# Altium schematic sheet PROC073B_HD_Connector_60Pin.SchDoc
size 431 x 279 mm; Date: Not shown in title block; ApprovedBy: Not shown in title block; CheckedBy: Not shown in title block; Author: Not shown in title block; CompanyName: Not shown in title block; Engineer: Not shown in title block; Organization: Not shown in title block; Address1: Not shown in title block; Address2: Not shown in title block; Address3: Not shown in title block; Address4: Not shown in title block; DocumentNumber: 1; Revision: Use project parameter SCH_Rev; SheetNumber: 7; SheetTotal: 9; PageSetup: Record=PageOptions¦CenterHorizontal=True¦CenterVertical=True¦PrintScale=1.00¦XCorrection=1.00¦YCorrection=1.00¦PrintKind=0¦BorderSize=5000000¦LeftOffset=0¦BottomOffset=0¦Orientation=2¦PaperLength=1000¦PaperWidth=1000¦Scale=100¦PaperSource=15¦PrintQuality=600¦MediaType=1¦DitherType=10¦PaperKind=Letter¦PrintScaleMode=1
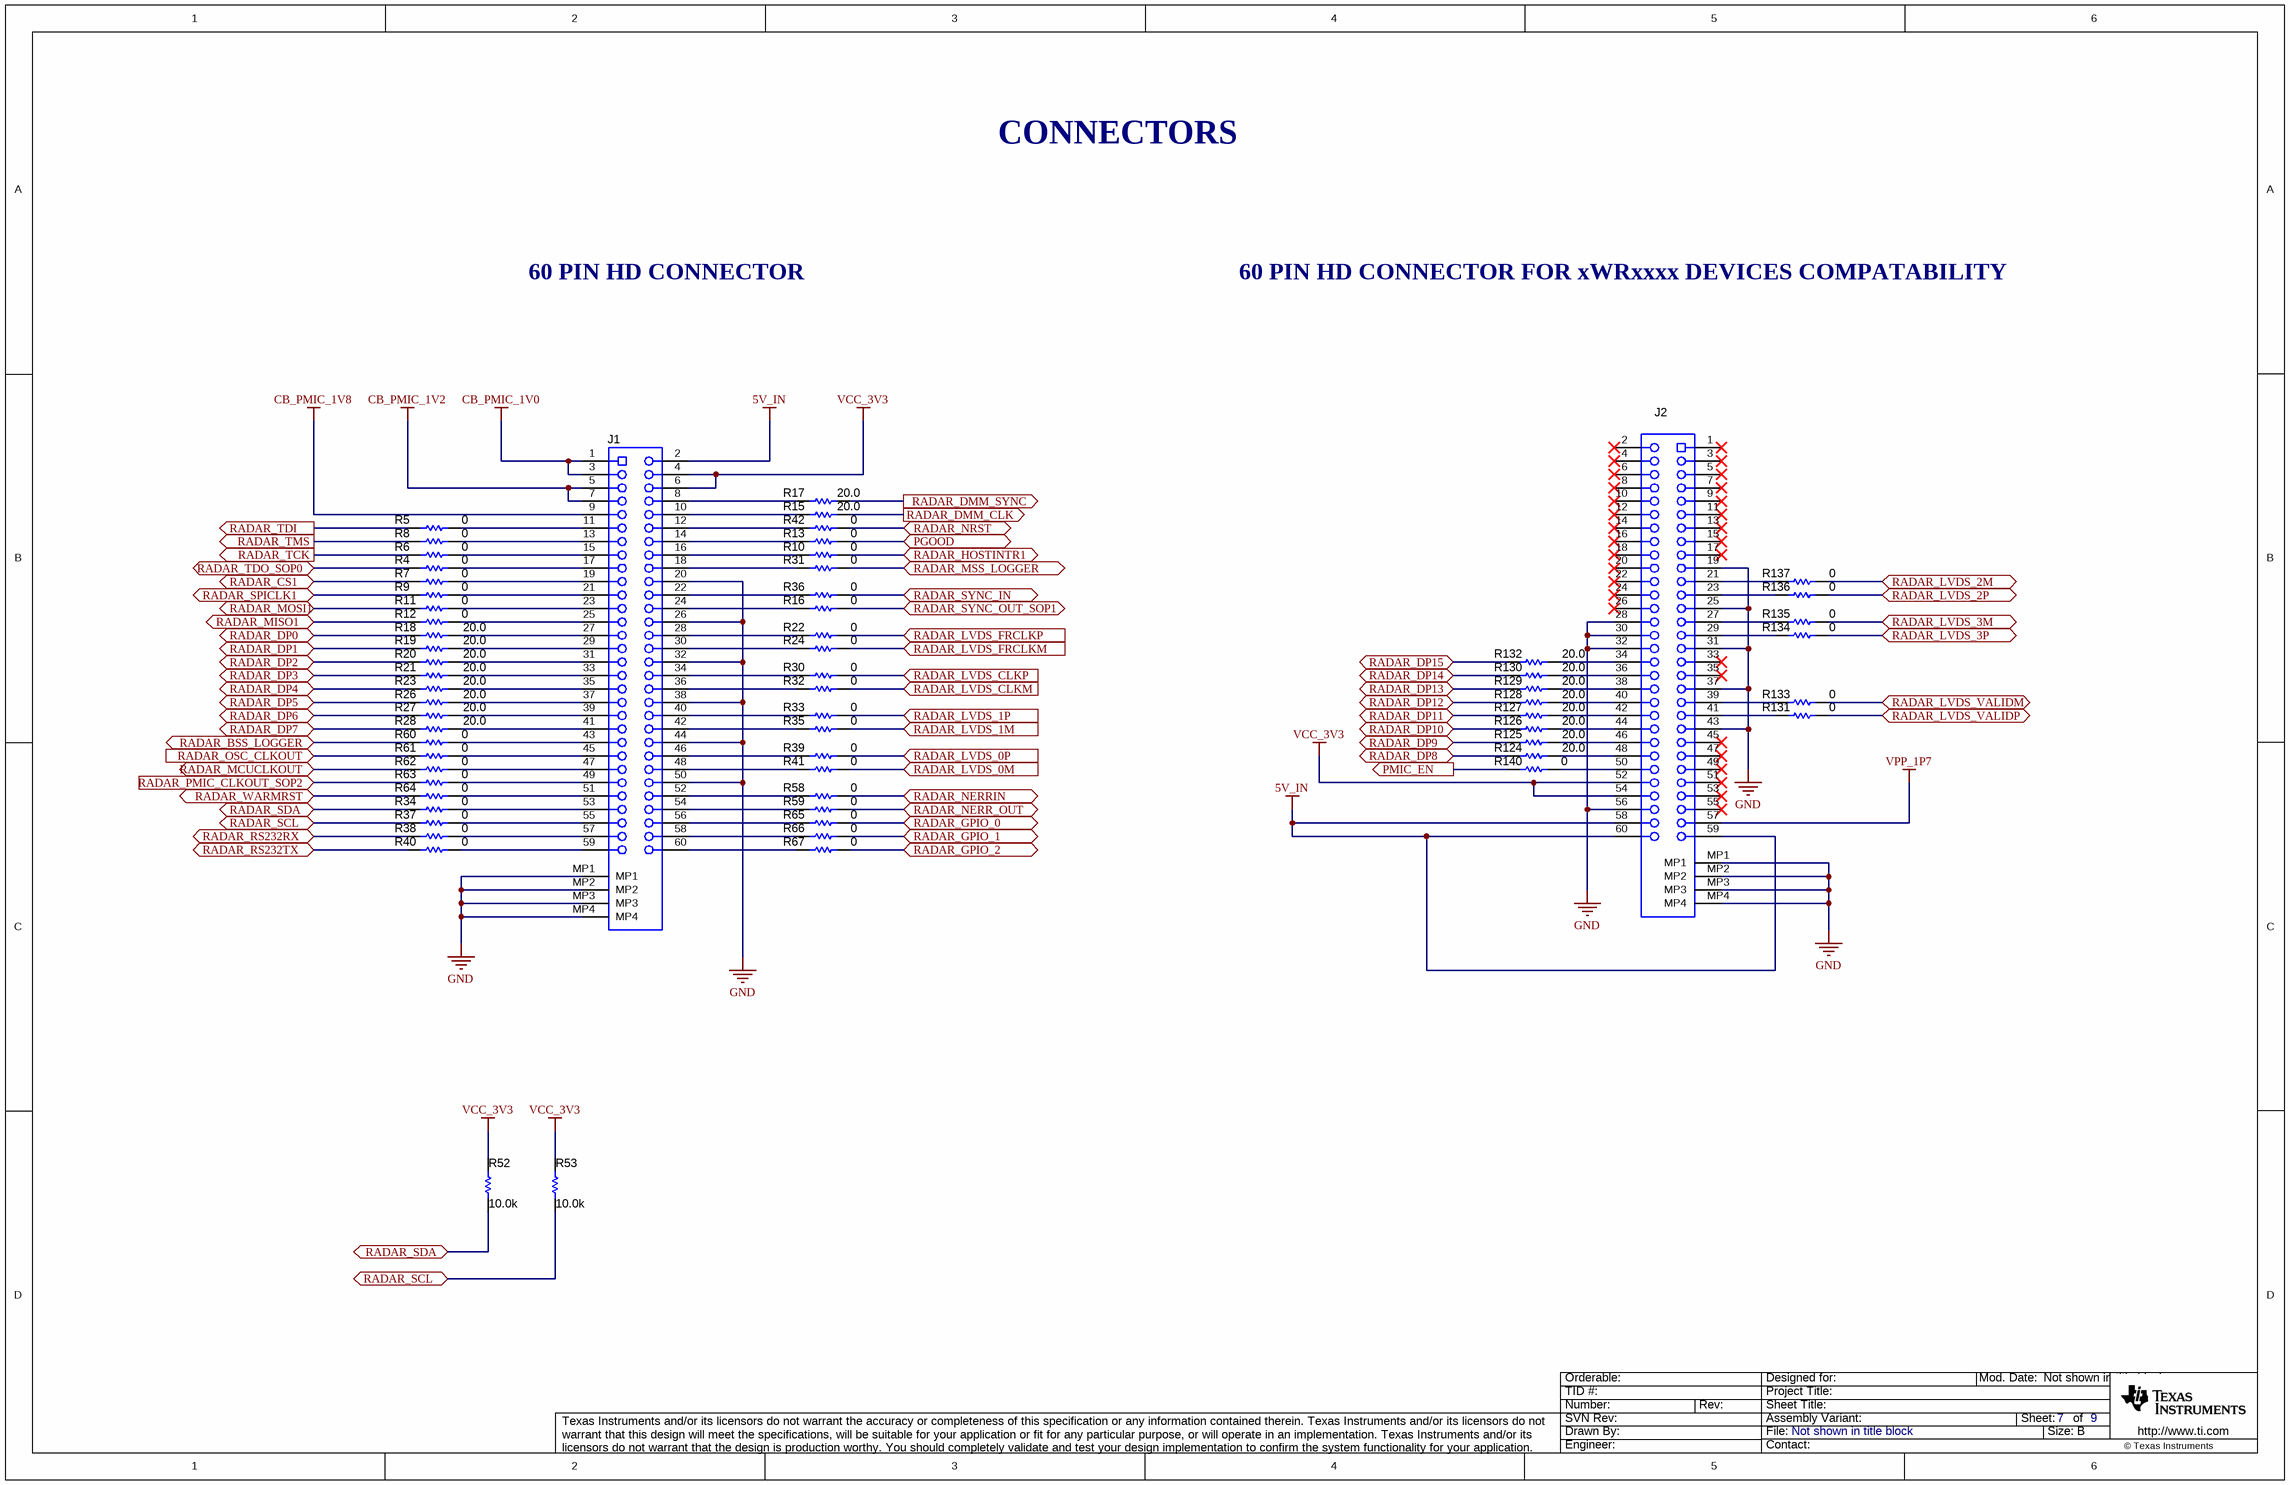
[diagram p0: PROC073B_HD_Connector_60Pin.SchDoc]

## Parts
J1  QSH-030-01-L-D-A  [Samtec_QSH-030-01-X-D-A]  (value not drawn)
J2  QSH-030-01-L-D-A  [Samtec_QSH-030-01-X-D-A]  (value not drawn)
R4  ValueDisplayed: 0  [0201_Silk]  (hidden comment: CRCW02010000Z0ED)
R5  ValueDisplayed: 0  [0201_Silk]  (hidden comment: CRCW02010000Z0ED)
R6  ValueDisplayed: 0  [0201_Silk]  (hidden comment: CRCW02010000Z0ED)
R7  ValueDisplayed: 0  [0201_Silk]  (hidden comment: CRCW02010000Z0ED)
R8  ValueDisplayed: 0  [0201_Silk]  (hidden comment: CRCW02010000Z0ED)
R9  ValueDisplayed: 0  [0201_Silk]  (hidden comment: CRCW02010000Z0ED)
R10  ValueDisplayed: 0  [0201_Silk]  (hidden comment: CRCW02010000Z0ED)
R11  ValueDisplayed: 0  [0201_Silk]  (hidden comment: CRCW02010000Z0ED)
R12  ValueDisplayed: 0  [0201_Silk]  (hidden comment: CRCW02010000Z0ED)
R13  ValueDisplayed: 0  [0201_Silk]  (hidden comment: CRCW02010000Z0ED)
R15  ValueDisplayed: 20.0  [0201_033]  (hidden comment: CRCW020120R0FNED)
R16  ValueDisplayed: 0  [0201_Silk]  (hidden comment: CRCW02010000Z0ED)
R17  ValueDisplayed: 20.0  [0201_033]  (hidden comment: CRCW020120R0FNED)
R18  ValueDisplayed: 20.0  [0201_033]  (hidden comment: CRCW020120R0FNED)
R19  ValueDisplayed: 20.0  [0201_033]  (hidden comment: CRCW020120R0FNED)
R20  ValueDisplayed: 20.0  [0201_033]  (hidden comment: CRCW020120R0FNED)
R21  ValueDisplayed: 20.0  [0201_033]  (hidden comment: CRCW020120R0FNED)
R22  ValueDisplayed: 0  [0201_Silk]  (hidden comment: CRCW02010000Z0ED)
R23  ValueDisplayed: 20.0  [0201_033]  (hidden comment: CRCW020120R0FNED)
R24  ValueDisplayed: 0  [0201_Silk]  (hidden comment: CRCW02010000Z0ED)
R26  ValueDisplayed: 20.0  [0201_033]  (hidden comment: CRCW020120R0FNED)
R27  ValueDisplayed: 20.0  [0201_033]  (hidden comment: CRCW020120R0FNED)
R28  ValueDisplayed: 20.0  [0201_033]  (hidden comment: CRCW020120R0FNED)
R30  ValueDisplayed: 0  [0201_Silk]  (hidden comment: CRCW02010000Z0ED)
R31  ValueDisplayed: 0  [0201_Silk]  (hidden comment: CRCW02010000Z0ED)
R32  ValueDisplayed: 0  [0201_Silk]  (hidden comment: CRCW02010000Z0ED)
R33  ValueDisplayed: 0  [0201_Silk]  (hidden comment: CRCW02010000Z0ED)
R34  ValueDisplayed: 0  [0201_Silk]  (hidden comment: CRCW02010000Z0ED)
R35  ValueDisplayed: 0  [0201_Silk]  (hidden comment: CRCW02010000Z0ED)
R36  ValueDisplayed: 0  [0201_Silk]  (hidden comment: CRCW02010000Z0ED)
R37  ValueDisplayed: 0  [0201_Silk]  (hidden comment: CRCW02010000Z0ED)
R38  ValueDisplayed: 0  [0201_Silk]  (hidden comment: CRCW02010000Z0ED)
R39  ValueDisplayed: 0  [0201_Silk]  (hidden comment: CRCW02010000Z0ED)
R40  ValueDisplayed: 0  [0201_Silk]  (hidden comment: CRCW02010000Z0ED)
R41  ValueDisplayed: 0  [0201_Silk]  (hidden comment: CRCW02010000Z0ED)
R42  ValueDisplayed: 0  [0201_Silk]  (hidden comment: CRCW02010000Z0ED)
R52  ValueDisplayed: 10.0k  [0402L]  (hidden comment: CRCW040210K0FKED)
R53  ValueDisplayed: 10.0k  [0402L]  (hidden comment: CRCW040210K0FKED)
R58  ValueDisplayed: 0  [0201_Silk]  (hidden comment: CRCW02010000Z0ED)
R59  ValueDisplayed: 0  [0201_Silk]  (hidden comment: CRCW02010000Z0ED)
R60  ValueDisplayed: 0  [0201_Silk]  (hidden comment: CRCW02010000Z0ED)
R61  ValueDisplayed: 0  [0201_Silk]  (hidden comment: CRCW02010000Z0ED)
R62  ValueDisplayed: 0  [0201_Silk]  (hidden comment: CRCW02010000Z0ED)
R63  ValueDisplayed: 0  [0201_Silk]  (hidden comment: CRCW02010000Z0ED)
R64  ValueDisplayed: 0  [0201_Silk]  (hidden comment: CRCW02010000Z0ED)
R65  ValueDisplayed: 0  [0201_Silk]  (hidden comment: CRCW02010000Z0ED)
R66  ValueDisplayed: 0  [0201_Silk]  (hidden comment: CRCW02010000Z0ED)
R67  ValueDisplayed: 0  [0201_Silk]  (hidden comment: CRCW02010000Z0ED)
R124  ValueDisplayed: 20.0  [0201_033]  (hidden comment: CRCW020120R0FNED)
R125  ValueDisplayed: 20.0  [0201_033]  (hidden comment: CRCW020120R0FNED)
R126  ValueDisplayed: 20.0  [0201_033]  (hidden comment: CRCW020120R0FNED)
R127  ValueDisplayed: 20.0  [0201_033]  (hidden comment: CRCW020120R0FNED)
R128  ValueDisplayed: 20.0  [0201_033]  (hidden comment: CRCW020120R0FNED)
R129  ValueDisplayed: 20.0  [0201_033]  (hidden comment: CRCW020120R0FNED)
R130  ValueDisplayed: 20.0  [0201_033]  (hidden comment: CRCW020120R0FNED)
R131  ValueDisplayed: 0  [0201_Silk]  (hidden comment: CRCW02010000Z0ED)
R132  ValueDisplayed: 20.0  [0201_033]  (hidden comment: CRCW020120R0FNED)
R133  ValueDisplayed: 0  [0201_Silk]  (hidden comment: CRCW02010000Z0ED)
R134  ValueDisplayed: 0  [0201_Silk]  (hidden comment: CRCW02010000Z0ED)
R135  ValueDisplayed: 0  [0201_Silk]  (hidden comment: CRCW02010000Z0ED)
R136  ValueDisplayed: 0  [0201_Silk]  (hidden comment: CRCW02010000Z0ED)
R137  ValueDisplayed: 0  [0201_Silk]  (hidden comment: CRCW02010000Z0ED)
R140  ValueDisplayed: 0  [0201_Silk]  (hidden comment: CRCW02010000Z0ED)

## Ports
PGOOD, PMIC_EN (out), RADAR_BSS_LOGGER, RADAR_CS1 (bidir), RADAR_DMM_CLK (out), RADAR_DMM_SYNC (out), RADAR_DP0 (bidir), RADAR_DP1 (bidir), RADAR_DP2 (bidir), RADAR_DP3 (bidir), RADAR_DP4 (bidir), RADAR_DP5 (bidir), RADAR_DP6 (bidir), RADAR_DP7 (bidir), RADAR_DP8, RADAR_DP9, RADAR_DP10, RADAR_DP11, RADAR_DP12, RADAR_DP13, RADAR_DP14, RADAR_DP15, RADAR_GPIO_0 (bidir), RADAR_GPIO_1 (bidir), RADAR_GPIO_2 (bidir), RADAR_HOSTINTR1, RADAR_LVDS_0M (in), RADAR_LVDS_0P (in), RADAR_LVDS_1M (in), RADAR_LVDS_1P (in), RADAR_LVDS_2M, RADAR_LVDS_2P, RADAR_LVDS_3M, RADAR_LVDS_3P, RADAR_LVDS_CLKM (in), RADAR_LVDS_CLKP (in), RADAR_LVDS_FRCLKM (in), RADAR_LVDS_FRCLKP (in), RADAR_LVDS_VALIDM, RADAR_LVDS_VALIDP, RADAR_MCUCLKOUT, RADAR_MISO1, RADAR_MOSI1, RADAR_MSS_LOGGER, RADAR_NERR_OUT, RADAR_NERRIN, RADAR_NRST, RADAR_OSC_CLKOUT (in), RADAR_PMIC_CLKOUT_SOP2 (in), RADAR_RS232RX, RADAR_RS232TX, RADAR_SCL, RADAR_SDA, RADAR_SPICLK1 (bidir), RADAR_SYNC_IN, RADAR_SYNC_OUT_SOP1, RADAR_TCK (out), RADAR_TDI (out), RADAR_TDO_SOP0, RADAR_TMS (out), RADAR_WARMRST

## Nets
5V_IN: J1.2 J2.58 J2.59 J2.60
CB_PMIC_1V0: J1.1 J1.3
CB_PMIC_1V2: J1.5 J1.7
CB_PMIC_1V8: J1.9
GND: J1.20 J1.26 J1.32 J1.38 J1.44 J1.50 J1.MP1 J1.MP2 J1.MP3 J1.MP4 J2.19 J2.25 J2.28 J2.30 J2.31 J2.32 J2.37 J2.43 J2.56 J2.MP1 J2.MP2 J2.MP3 J2.MP4
VCC_3V3: J1.4 J1.6 J2.52 J2.54 R52.2 R53.2
VPP_1P7: J2.57
PGOOD: R13.2 ; port PGOOD
PMIC_EN: R140.1 ; port PMIC_EN
RADAR_BSS_LOGGER: R60.2 ; port RADAR_BSS_LOGGER
RADAR_CS1: R7.1 ; port RADAR_CS1
RADAR_DMM_CLK: R15.1 ; port RADAR_DMM_CLK
RADAR_DMM_SYNC: R17.1 ; port RADAR_DMM_SYNC
RADAR_DP0: R18.1 ; port RADAR_DP0
RADAR_DP1: R19.1 ; port RADAR_DP1
RADAR_DP2: R20.1 ; port RADAR_DP2
RADAR_DP3: R21.1 ; port RADAR_DP3
RADAR_DP4: R23.1 ; port RADAR_DP4
RADAR_DP5: R26.1 ; port RADAR_DP5
RADAR_DP6: R27.1 ; port RADAR_DP6
RADAR_DP7: R28.1 ; port RADAR_DP7
RADAR_DP8: R124.1 ; port RADAR_DP8
RADAR_DP9: R125.1 ; port RADAR_DP9
RADAR_DP10: R126.1 ; port RADAR_DP10
RADAR_DP11: R127.1 ; port RADAR_DP11
RADAR_DP12: R128.1 ; port RADAR_DP12
RADAR_DP13: R129.1 ; port RADAR_DP13
RADAR_DP14: R130.1 ; port RADAR_DP14
RADAR_DP15: R132.1 ; port RADAR_DP15
RADAR_GPIO_0: R65.1 ; port RADAR_GPIO_0
RADAR_GPIO_1: R66.2 ; port RADAR_GPIO_1
RADAR_GPIO_2: R67.2 ; port RADAR_GPIO_2
RADAR_HOSTINTR1: R10.2 ; port RADAR_HOSTINTR1
RADAR_LVDS_0M: R41.2 ; port RADAR_LVDS_0M
RADAR_LVDS_0P: R39.2 ; port RADAR_LVDS_0P
RADAR_LVDS_1M: R35.2 ; port RADAR_LVDS_1M
RADAR_LVDS_1P: R33.2 ; port RADAR_LVDS_1P
RADAR_LVDS_2M: R137.2 ; port RADAR_LVDS_2M
RADAR_LVDS_2P: R136.2 ; port RADAR_LVDS_2P
RADAR_LVDS_3M: R135.2 ; port RADAR_LVDS_3M
RADAR_LVDS_3P: R134.2 ; port RADAR_LVDS_3P
RADAR_LVDS_CLKM: R32.2 ; port RADAR_LVDS_CLKM
RADAR_LVDS_CLKP: R30.2 ; port RADAR_LVDS_CLKP
RADAR_LVDS_FRCLKM: R24.2 ; port RADAR_LVDS_FRCLKM
RADAR_LVDS_FRCLKP: R22.2 ; port RADAR_LVDS_FRCLKP
RADAR_LVDS_VALIDM: R133.2 ; port RADAR_LVDS_VALIDM
RADAR_LVDS_VALIDP: R131.2 ; port RADAR_LVDS_VALIDP
RADAR_MCUCLKOUT: R62.2 ; port RADAR_MCUCLKOUT
RADAR_MISO1: R12.2 ; port RADAR_MISO1
RADAR_MOSI1: R11.1 ; port RADAR_MOSI1
RADAR_MSS_LOGGER: R31.2 ; port RADAR_MSS_LOGGER
RADAR_NERR_OUT: R59.2 ; port RADAR_NERR_OUT
RADAR_NERRIN: R58.2 ; port RADAR_NERRIN
RADAR_NRST: R42.1 ; port RADAR_NRST
RADAR_OSC_CLKOUT: R61.2 ; port RADAR_OSC_CLKOUT
RADAR_PMIC_CLKOUT_SOP2: R63.2 ; port RADAR_PMIC_CLKOUT_SOP2
RADAR_RS232RX: R38.1 ; port RADAR_RS232RX
RADAR_RS232TX: R40.1 ; port RADAR_RS232TX
RADAR_SCL: R37.1 R53.1 ; port RADAR_SCL
RADAR_SDA: R34.1 R52.1 ; port RADAR_SDA
RADAR_SPICLK1: R9.1 ; port RADAR_SPICLK1
RADAR_SYNC_IN: R36.2 ; port RADAR_SYNC_IN
RADAR_SYNC_OUT_SOP1: R16.2 ; port RADAR_SYNC_OUT_SOP1
RADAR_TCK: R6.2 ; port RADAR_TCK
RADAR_TDI: R5.1 ; port RADAR_TDI
RADAR_TDO_SOP0: R4.2 ; port RADAR_TDO_SOP0
RADAR_TMS: R8.2 ; port RADAR_TMS
RADAR_WARMRST: R64.2 ; port RADAR_WARMRST
NetJ1_8: J1.8 R17.2
NetJ1_10: J1.10 R15.2
NetJ1_11: J1.11 R5.2
NetJ1_12: J1.12 R42.2
NetJ1_13: J1.13 R8.1
NetJ1_14: J1.14 R13.1
NetJ1_15: J1.15 R6.1
NetJ1_16: J1.16 R10.1
NetJ1_17: J1.17 R4.1
NetJ1_18: J1.18 R31.1
NetJ1_19: J1.19 R7.2
NetJ1_21: J1.21 R9.2
NetJ1_22: J1.22 R36.1
NetJ1_23: J1.23 R11.2
NetJ1_24: J1.24 R16.1
NetJ1_25: J1.25 R12.1
NetJ1_27: J1.27 R18.2
NetJ1_28: J1.28 R22.1
NetJ1_29: J1.29 R19.2
NetJ1_30: J1.30 R24.1
NetJ1_31: J1.31 R20.2
NetJ1_33: J1.33 R21.2
NetJ1_34: J1.34 R30.1
NetJ1_35: J1.35 R23.2
NetJ1_36: J1.36 R32.1
NetJ1_37: J1.37 R26.2
NetJ1_39: J1.39 R27.2
NetJ1_40: J1.40 R33.1
NetJ1_41: J1.41 R28.2
NetJ1_42: J1.42 R35.1
NetJ1_43: J1.43 R60.1
NetJ1_45: J1.45 R61.1
NetJ1_46: J1.46 R39.1
NetJ1_47: J1.47 R62.1
NetJ1_48: J1.48 R41.1
NetJ1_49: J1.49 R63.1
NetJ1_51: J1.51 R64.1
NetJ1_52: J1.52 R58.1
NetJ1_53: J1.53 R34.2
NetJ1_54: J1.54 R59.1
NetJ1_55: J1.55 R37.2
NetJ1_56: J1.56 R65.2
NetJ1_57: J1.57 R38.2
NetJ1_58: J1.58 R66.1
NetJ1_59: J1.59 R40.2
NetJ1_60: J1.60 R67.1
NetJ2_21: J2.21 R137.1
NetJ2_23: J2.23 R136.1
NetJ2_27: J2.27 R135.1
NetJ2_29: J2.29 R134.1
NetJ2_34: J2.34 R132.2
NetJ2_36: J2.36 R130.2
NetJ2_38: J2.38 R129.2
NetJ2_39: J2.39 R133.1
NetJ2_40: J2.40 R128.2
NetJ2_41: J2.41 R131.1
NetJ2_42: J2.42 R127.2
NetJ2_44: J2.44 R126.2
NetJ2_46: J2.46 R125.2
NetJ2_48: J2.48 R124.2
NetJ2_50: J2.50 R140.2

Not connected (* = marked no-connect by the designer): J2 1* 2* 3* 4* 5* 6* 7* 8* 9* 10* 11* 12* 13* 14* 15* 16* 17* 18* 20* 22* 24* 26* 33* 35* 45* 47* 49* 51* 53* 55*

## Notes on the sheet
- CONNECTORS
- 60 PIN HD CONNECTOR
- 60 PIN HD CONNECTOR FOR xWRxxxx DEVICES COMPATABILITY

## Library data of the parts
J1 J2 = CMP-0075524-1: Receptacle, 0.5 mm, 30x2, Gold, TH; Manufacturer: Samtec; Pitch_mm: 0.5; Gender: Female; Green_REACh: Passed; CT: False; Shrouded: N; RowSpacing_mm: 5.73; Green_Lifecycle: Active; Row_Count: 2
R4-R13 R16 R22 R24 R30-R37 R39 R41 R42 R58-R67 R131 R133-R137 R140 = CMP-0027008-3: RES, 0, 5%, 0.05 W, 0201; Manufacturer: Vishay-Dale; Power_W: 50mW; TempCo: ppm/C; Value_Code: 0000; U/M: EA; Value: 0; EIA_Code: E24; SizeX_mm: 0.6; SizeY_mm: 0.3; SizeZ_mm: 0.26; Value2: 0.05W; SizeArea_mm2: 0.18; AEC Qualified: N; AEC Category: Q200
R15 R17-R21 R23 R26-R28 R124-R130 R132 = CMP-0078192-1: RES, 20.0, 1%, 0.05 W, 0201; Manufacturer: Vishay-Dale; Value_Code: 20R0; SizeArea_mm2: 0.18; AEC Qualified: N; AEC Category: Q200; Res_ohm: 20; Value: 20.0; SizeZ_mm: 0.33; EIA_Code: E96; TempCo: 200 ppm/C; Power_W: 50mW; VDC_V: 30V; SizeY_mm: 0.3; Value2: 0.05W; U/M: EA; SizeX_mm: 0.6
R38 R40 = CMP-0027008-3: RES, 0, 5%, 0.05 W, 0201; Manufacturer: Vishay-Dale; Power_W: 50mW; TempCo: ppm/C; Value_Code: 0000; U/M: EA; Value: 0; EIA_Code: E24; SizeX_mm: 0.6; SizeY_mm: 0.3; SizeZ_mm: 0.26; Value2: 0.05W; SizeArea_mm2: 0.18; CompType: Resistor; AEC Qualified: N; AEC Category: Q200; INSTALATION: DNP
R52 R53 = CMP-0025958-2: RES, 10.0 k, 1%, 0.063 W, 0402; Manufacturer: Vishay-Dale; Power_W: 63mW; TempCo: 100 ppm/C; Value_Code: 10k0; U/M: EA; Value: 10.0k; EIA_Code: E96; Res_ohm: 10k; SizeX_mm: 1; SizeY_mm: 0.5; SizeZ_mm: 0.6; Value2: 0.063W; VDC_V: 50V; AEC Category: Q200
